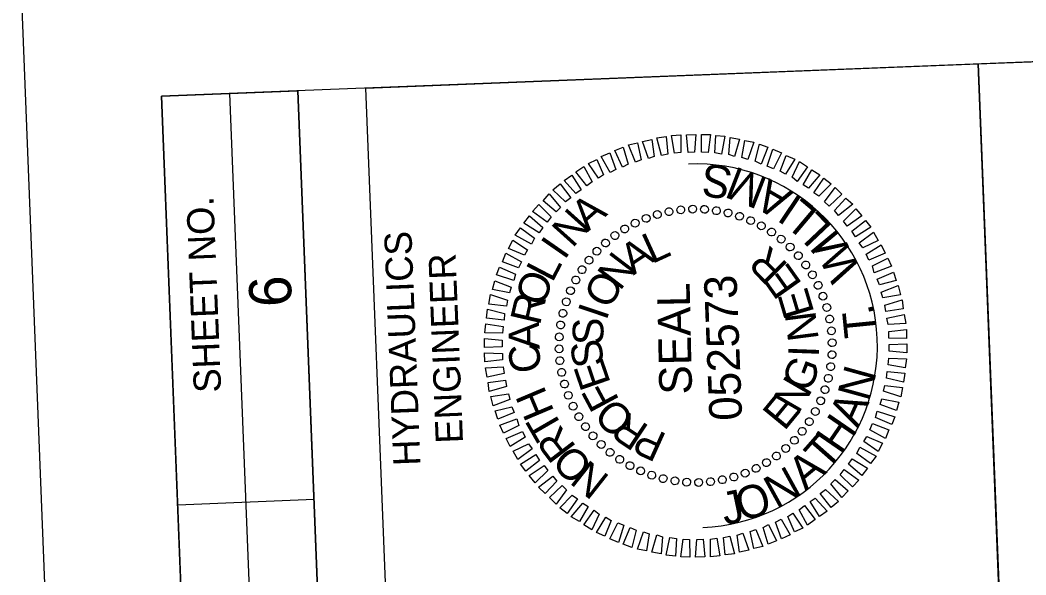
# Model space of a CAD drawing. Extents: x 1627804 to 1628970, y 763730 to 765944.
# Drawn here: x 1627803.6 to 1627988.3, y 765588.9 to 765690.7 of the extents above; entities that cross this region are included whole.
import ezdxf

# ---------------------------------------------------------------- set-up
doc = ezdxf.new("R2010")
doc.units = 0
for name, color, linetype in [('Exist Property Line Text', 7, 'Continuous'), ('Exist Property Owner Number CELL', 7, 'Continuous'), ('Exist Right of Way Easement Line', 7, 'Continuous'), ('Exist Right of Way Monument Text', 7, 'Continuous'), ('Exist Utilities Gas UG Line', 7, 'Continuous'), ('Exist Utilities Gas UG Line Text', 7, 'Continuous'), ('Raster_Level_0', 7, 'Continuous'), ('Scratch_Level_2', 7, 'Continuous')]:
    doc.layers.add(name, color=color, linetype=linetype)

msp = doc.modelspace()

# ---------------------------------------------------------------- linework, layer by layer
at = {"layer": 'Exist Property Owner Number CELL'}
msp.add_arc((1627927.63, 765630.96), 33.36, 272.2582, 92.2582, dxfattribs=at)
at = {"layer": 'Exist Right of Way Monument Text'}
for p, q in [((1627862.5, 765477.84), (1627854.61, 765677.73)), ((1627850.01, 765477.34), (1627842.12, 765677.24)), ((1627832.59, 765601.8), (1627857.57, 765602.79))]:
    msp.add_line(p, q, dxfattribs=at)
for points in [[(1627829.58, 765676.74), (1627888.69, 764177.91), (1628937.87, 764219.28), (1628878.77, 765718.12)], [(1627871.04, 765578.3), (1627867.1, 765678.22), (1627979.52, 765682.66), (1627983.46, 765582.73)], [(1627837.47, 765476.85), (1627829.58, 765676.74), (1627854.61, 765677.73), (1627862.5, 765477.84)]]:
    msp.add_lwpolyline(points, close=True, dxfattribs=at)
at = {"layer": 'Exist Utilities Gas UG Line'}
msp.add_lwpolyline([(1628969.75, 764045.4), (1628902.76, 765744.08), (1627803.62, 765700.74), (1627870.6, 764002.06)], close=True, dxfattribs=at)
at = {"layer": 'Exist Utilities Gas UG Line Text'}
for p, q in [((1627979.52, 765682.66), (1628011.47, 765683.92)), ((1627987.38, 765482.76), (1627979.5, 765682.65))]:
    msp.add_line(p, q, dxfattribs=at)
at = {"layer": 'Scratch_Level_2'}
for p, q in [((1627922.76, 765655.53), (1627922.76, 765655.53)), ((1627924.89, 765655.92), (1627924.89, 765655.92)), ((1627927.09, 765656.05), (1627927.09, 765656.05)), ((1627929.3, 765655.99), (1627929.3, 765655.99)), ((1627931.46, 765655.73), (1627931.46, 765655.73)), ((1627933.57, 765655.36), (1627933.57, 765655.36)), ((1627916.53, 765653.49), (1627916.53, 765653.49)), ((1627918.5, 765654.36), (1627918.5, 765654.36)), ((1627920.58, 765655.05), (1627920.58, 765655.05)), ((1627935.7, 765654.74), (1627935.7, 765654.74)), ((1627937.73, 765653.92), (1627937.73, 765653.92)), ((1627914.62, 765652.41), (1627914.62, 765652.41)), ((1627939.72, 765653), (1627939.72, 765653)), ((1627941.57, 765651.82), (1627941.57, 765651.82)), ((1627911.07, 765649.87), (1627911.07, 765649.87)), ((1627912.77, 765651.19), (1627912.77, 765651.19)), ((1627943.37, 765650.54), (1627943.37, 765650.54)), ((1627909.48, 765648.3), (1627909.48, 765648.3)), ((1627944.98, 765649.1), (1627944.98, 765649.1)), ((1627908.04, 765646.7), (1627908.04, 765646.7)), ((1627946.54, 765647.51), (1627946.54, 765647.51)), ((1627906.76, 765644.89), (1627906.76, 765644.89)), ((1627947.86, 765645.81), (1627947.86, 765645.81)), ((1627905.59, 765643.05), (1627905.59, 765643.05)), ((1627949.08, 765643.96), (1627949.08, 765643.96)), ((1627904.66, 765641.06), (1627904.66, 765641.06)), ((1627950.16, 765642.05), (1627950.16, 765642.05)), ((1627903.84, 765639.02), (1627903.84, 765639.02)), ((1627951.04, 765640.08), (1627951.04, 765640.08)), ((1627903.23, 765636.9), (1627903.23, 765636.9)), ((1627951.72, 765638.01), (1627951.72, 765638.01)), ((1627952.21, 765635.83), (1627952.21, 765635.83)), ((1627902.86, 765634.78), (1627902.86, 765634.78)), ((1627952.59, 765633.69), (1627952.59, 765633.69)), ((1627902.6, 765632.62), (1627902.6, 765632.62)), ((1627952.73, 765631.49), (1627952.73, 765631.49)), ((1627902.53, 765630.42), (1627902.53, 765630.42)), ((1627927.63, 765630.96), (1627927.63, 765630.96)), ((1627952.67, 765629.29), (1627952.67, 765629.29)), ((1627902.67, 765628.22), (1627902.67, 765628.22)), ((1627903.05, 765626.08), (1627903.05, 765626.08)), ((1627952.4, 765627.13), (1627952.4, 765627.13)), ((1627903.54, 765623.9), (1627903.54, 765623.9)), ((1627952.03, 765625.01), (1627952.03, 765625.01)), ((1627951.42, 765622.89), (1627951.42, 765622.89)), ((1627904.22, 765621.83), (1627904.22, 765621.83)), ((1627950.6, 765620.85), (1627950.6, 765620.85)), ((1627905.1, 765619.86), (1627905.1, 765619.86)), ((1627949.67, 765618.86), (1627949.67, 765618.86)), ((1627906.18, 765617.95), (1627906.18, 765617.95)), ((1627948.5, 765617.02), (1627948.5, 765617.02)), ((1627907.4, 765616.1), (1627907.4, 765616.1)), ((1627947.22, 765615.21), (1627947.22, 765615.21)), ((1627908.72, 765614.4), (1627908.72, 765614.4)), ((1627910.28, 765612.81), (1627910.28, 765612.81)), ((1627945.78, 765613.61), (1627945.78, 765613.61)), ((1627911.89, 765611.37), (1627911.89, 765611.37)), ((1627944.19, 765612.04), (1627944.19, 765612.04)), ((1627913.69, 765610.09), (1627913.69, 765610.09)), ((1627940.64, 765609.5), (1627940.64, 765609.5)), ((1627942.49, 765610.73), (1627942.49, 765610.73)), ((1627915.54, 765608.91), (1627915.54, 765608.91)), ((1627917.53, 765607.99), (1627917.53, 765607.99)), ((1627919.56, 765607.17), (1627919.56, 765607.17)), ((1627936.76, 765607.55), (1627936.76, 765607.55)), ((1627938.73, 765608.43), (1627938.73, 765608.43)), ((1627921.69, 765606.55), (1627921.69, 765606.55)), ((1627923.8, 765606.19), (1627923.8, 765606.19)), ((1627925.97, 765605.92), (1627925.97, 765605.92)), ((1627928.17, 765605.86), (1627928.17, 765605.86)), ((1627930.37, 765605.99), (1627930.37, 765605.99)), ((1627932.5, 765606.38), (1627932.5, 765606.38)), ((1627934.69, 765606.86), (1627934.69, 765606.86))]:
    msp.add_line(p, q, dxfattribs=at)
for points in [[(1627916.59, 765664.65), (1627915.32, 765667.8), (1627916.96, 765668.16), (1627917.63, 765665.04)], [(1627918.97, 765665.34), (1627917.9, 765668.45), (1627919.58, 765668.82), (1627920.01, 765665.68)], [(1627921.35, 765665.88), (1627920.52, 765669.1), (1627922.21, 765669.32), (1627922.54, 765666.13)], [(1627923.74, 765666.28), (1627923.21, 765669.51), (1627924.9, 765669.68), (1627924.93, 765666.43)], [(1627926.23, 765666.43), (1627925.95, 765669.67), (1627927.65, 765669.74), (1627927.43, 765666.48)], [(1627928.73, 765666.48), (1627928.7, 765669.73), (1627930.36, 765669.69), (1627929.93, 765666.42)], [(1627931.14, 765666.32), (1627931.31, 765669.53), (1627933.02, 765669.4), (1627932.35, 765666.12)], [(1627933.7, 765666.02), (1627933.98, 765669.14), (1627935.69, 765668.85), (1627934.77, 765665.66)], [(1627936.13, 765665.47), (1627936.65, 765668.59), (1627938.32, 765668.31), (1627937.19, 765665.11)], [(1627911.91, 765662.76), (1627910.3, 765665.65), (1627911.87, 765666.36), (1627912.99, 765663.3)], [(1627914.23, 765663.75), (1627912.81, 765666.75), (1627914.34, 765667.36), (1627915.26, 765664.29)], [(1627938.55, 765664.81), (1627939.33, 765667.95), (1627940.91, 765667.36), (1627939.63, 765664.3)], [(1627940.79, 765663.9), (1627941.82, 765667.04), (1627943.4, 765666.35), (1627941.91, 765663.44)], [(1627909.81, 765661.68), (1627907.95, 765664.41), (1627909.47, 765665.12), (1627910.73, 765662.31)], [(1627943.13, 765662.99), (1627944.27, 765665.89), (1627945.85, 765665.2), (1627944.1, 765662.43)], [(1627945.33, 765661.88), (1627946.71, 765664.73), (1627948.15, 765663.79), (1627946.26, 765661.11)], [(1627907.66, 765660.29), (1627905.66, 765662.86), (1627907.12, 765663.87), (1627908.63, 765661.03)], [(1627947.38, 765660.46), (1627948.98, 765663.22), (1627950.46, 765662.33), (1627948.36, 765659.84)], [(1627903.77, 765657.34), (1627901.43, 765659.55), (1627902.74, 765660.65), (1627904.74, 765658.07)], [(1627905.66, 765658.91), (1627903.47, 765661.28), (1627904.88, 765662.28), (1627906.59, 765659.55)], [(1627949.34, 765659.03), (1627951.19, 765661.71), (1627952.53, 765660.66), (1627950.27, 765658.37)], [(1627902.04, 765655.52), (1627899.61, 765657.57), (1627900.76, 765658.82), (1627902.81, 765656.3)], [(1627951.31, 765657.36), (1627953.26, 765659.99), (1627954.45, 765658.78), (1627952.14, 765656.59)], [(1627953.12, 765655.78), (1627955.23, 765658.06), (1627956.48, 765656.91), (1627953.86, 765654.86)], [(1627900.36, 765653.65), (1627897.69, 765655.59), (1627898.84, 765656.84), (1627901.08, 765654.63)], [(1627954.75, 765653.84), (1627957.06, 765656.08), (1627958.17, 765654.78), (1627955.44, 765652.92)], [(1627898.89, 765651.69), (1627896.07, 765653.43), (1627897.12, 765654.77), (1627899.55, 765652.67)], [(1627956.32, 765652), (1627958.8, 765653.95), (1627959.8, 765652.69), (1627956.97, 765650.93)], [(1627897.47, 765649.58), (1627894.51, 765651.22), (1627895.5, 765652.56), (1627898.03, 765650.7)], [(1627957.66, 765649.85), (1627960.28, 765651.81), (1627961.14, 765650.29), (1627958.3, 765648.93)], [(1627896.2, 765647.58), (1627893.3, 765648.82), (1627894.09, 765650.35), (1627896.76, 765648.55)], [(1627895.14, 765645.24), (1627892.15, 765646.37), (1627892.78, 765647.95), (1627895.65, 765646.36)], [(1627958.94, 765647.75), (1627961.68, 765649.46), (1627962.44, 765647.94), (1627959.44, 765646.67)], [(1627960.08, 765645.6), (1627962.93, 765647.01), (1627963.58, 765645.53), (1627960.43, 765644.36)], [(1627894.28, 765642.95), (1627891.09, 765643.98), (1627891.63, 765645.4), (1627894.59, 765644.11)], [(1627960.97, 765643.18), (1627963.93, 765644.45), (1627964.44, 765642.91), (1627961.37, 765642.14)], [(1627893.47, 765640.67), (1627890.34, 765641.29), (1627890.78, 765642.86), (1627893.78, 765641.73)], [(1627961.72, 765640.81), (1627964.82, 765641.98), (1627965.24, 765640.29), (1627962.01, 765639.77)], [(1627892.92, 765638.24), (1627889.65, 765638.61), (1627889.98, 765640.33), (1627893.12, 765639.3)], [(1627962.36, 765638.43), (1627965.53, 765639.36), (1627965.74, 765637.71), (1627962.56, 765637.24)], [(1627892.47, 765635.67), (1627889.25, 765636), (1627889.44, 765637.66), (1627892.57, 765636.88)], [(1627962.76, 765636.04), (1627965.93, 765636.72), (1627966.2, 765635.03), (1627962.95, 765634.85)], [(1627892.16, 765633.26), (1627888.91, 765633.33), (1627889.14, 765634.99), (1627892.31, 765634.47)], [(1627963.11, 765633.56), (1627966.34, 765633.93), (1627966.36, 765632.28), (1627963.1, 765632.35)], [(1627892.11, 765630.76), (1627888.86, 765630.63), (1627888.85, 765632.28), (1627892.11, 765631.96)], [(1627963.15, 765631.16), (1627966.4, 765631.28), (1627966.41, 765629.63), (1627963.15, 765629.95)], [(1627892.16, 765628.36), (1627888.92, 765627.98), (1627888.9, 765629.63), (1627892.16, 765629.56)], [(1627963.1, 765628.65), (1627966.35, 765628.58), (1627966.12, 765626.92), (1627962.95, 765627.44)], [(1627892.5, 765625.87), (1627889.33, 765625.19), (1627889.06, 765626.88), (1627892.31, 765627.06)], [(1627962.79, 765626.24), (1627966.01, 765625.91), (1627965.82, 765624.26), (1627962.69, 765625.03)], [(1627892.9, 765623.48), (1627889.73, 765622.56), (1627889.52, 765624.2), (1627892.7, 765624.67)], [(1627893.54, 765621.1), (1627890.44, 765619.93), (1627890.02, 765621.62), (1627893.25, 765622.14)], [(1627962.34, 765623.67), (1627965.61, 765623.3), (1627965.28, 765621.58), (1627962.14, 765622.61)], [(1627961.79, 765621.24), (1627964.92, 765620.62), (1627964.48, 765619.05), (1627961.48, 765620.18)], [(1627894.29, 765618.73), (1627891.33, 765617.46), (1627890.82, 765619), (1627893.89, 765619.77)], [(1627960.98, 765618.96), (1627964.17, 765617.94), (1627963.63, 765616.51), (1627960.67, 765617.8)], [(1627895.18, 765616.32), (1627892.34, 765614.9), (1627891.68, 765616.38), (1627894.83, 765617.55)], [(1627960.12, 765616.67), (1627963.12, 765615.54), (1627962.48, 765613.97), (1627959.61, 765615.55)], [(1627896.32, 765614.16), (1627893.58, 765612.45), (1627892.82, 765613.97), (1627895.82, 765615.24)], [(1627897.6, 765612.06), (1627894.98, 765610.1), (1627894.12, 765611.62), (1627896.96, 765612.98)], [(1627959.06, 765614.33), (1627961.96, 765613.09), (1627961.17, 765611.56), (1627958.5, 765613.36)], [(1627898.94, 765609.91), (1627896.46, 765607.96), (1627895.46, 765609.22), (1627898.29, 765610.98)], [(1627957.79, 765612.33), (1627960.75, 765610.69), (1627959.76, 765609.35), (1627957.23, 765611.21)], [(1627900.51, 765608.07), (1627898.2, 765605.83), (1627897.1, 765607.13), (1627899.82, 765608.99)], [(1627956.37, 765610.22), (1627959.19, 765608.48), (1627958.14, 765607.14), (1627955.71, 765609.24)], [(1627954.9, 765608.26), (1627957.57, 765606.32), (1627956.42, 765605.07), (1627954.18, 765607.28)], [(1627902.14, 765606.13), (1627900.03, 765603.85), (1627898.78, 765605), (1627901.4, 765607.05)], [(1627903.95, 765604.55), (1627902, 765601.92), (1627900.81, 765603.13), (1627903.12, 765605.32)], [(1627953.22, 765606.39), (1627955.65, 765604.34), (1627954.5, 765603.09), (1627952.45, 765605.61)], [(1627905.92, 765602.88), (1627904.07, 765600.2), (1627902.73, 765601.25), (1627904.99, 765603.54)], [(1627951.49, 765604.57), (1627953.83, 765602.37), (1627952.52, 765601.26), (1627950.52, 765603.84)], [(1627907.88, 765601.45), (1627906.29, 765598.69), (1627904.8, 765599.58), (1627906.9, 765602.07)], [(1627947.6, 765601.62), (1627949.6, 765599.05), (1627948.14, 765598.04), (1627946.63, 765600.88)], [(1627949.6, 765603), (1627951.79, 765600.63), (1627950.38, 765599.63), (1627948.67, 765602.36)], [(1627909.93, 765600.03), (1627908.55, 765597.18), (1627907.11, 765598.12), (1627909, 765600.8)], [(1627945.45, 765600.23), (1627947.31, 765597.5), (1627945.79, 765596.79), (1627944.53, 765599.6)], [(1627912.13, 765598.92), (1627910.99, 765596.02), (1627909.42, 765596.71), (1627911.16, 765599.48)], [(1627914.47, 765598.01), (1627913.44, 765594.87), (1627911.86, 765595.56), (1627913.35, 765598.47)], [(1627941.03, 765598.16), (1627942.45, 765595.16), (1627940.93, 765594.55), (1627940, 765597.62)], [(1627943.35, 765599.15), (1627944.96, 765596.26), (1627943.39, 765595.55), (1627942.27, 765598.61)], [(1627916.71, 765597.1), (1627915.93, 765593.97), (1627914.35, 765594.55), (1627915.64, 765597.61)], [(1627919.13, 765596.44), (1627918.61, 765593.32), (1627916.94, 765593.61), (1627918.07, 765596.8)], [(1627921.56, 765595.89), (1627921.28, 765592.78), (1627919.57, 765593.06), (1627920.49, 765596.25)], [(1627933.91, 765596.03), (1627934.74, 765592.81), (1627933.05, 765592.59), (1627932.72, 765595.78)], [(1627936.29, 765596.57), (1627937.37, 765593.46), (1627935.68, 765593.09), (1627935.25, 765596.23)], [(1627938.67, 765597.26), (1627939.94, 765594.11), (1627938.3, 765593.75), (1627937.63, 765596.87)], [(1627924.12, 765595.59), (1627923.95, 765592.38), (1627922.24, 765592.51), (1627922.91, 765595.79)], [(1627926.53, 765595.43), (1627926.56, 765592.18), (1627924.9, 765592.22), (1627925.33, 765595.49)], [(1627929.03, 765595.48), (1627929.31, 765592.24), (1627927.61, 765592.17), (1627927.83, 765595.44)], [(1627931.53, 765595.63), (1627932.05, 765592.4), (1627930.36, 765592.23), (1627930.33, 765595.48)]]:
    msp.add_lwpolyline(points, close=True, dxfattribs=at)
for centre, major_axis in [((1627918.54, 765654.33), (-0.261, 0.671)), ((1627920.61, 765655.03), (-0.202, 0.691)), ((1627922.73, 765655.55), (-0.141, 0.706)), ((1627924.9, 765655.89), (-0.078, 0.716)), ((1627927.08, 765656.03), (-0.016, 0.72)), ((1627929.27, 765655.98), (0.047, 0.718)), ((1627931.44, 765655.74), (0.109, 0.712)), ((1627933.59, 765655.32), (0.171, 0.699)), ((1627935.69, 765654.71), (0.231, 0.682)), ((1627916.53, 765653.45), (-0.319, 0.646)), ((1627937.73, 765653.91), (0.29, 0.659)), ((1627939.69, 765652.95), (0.346, 0.631)), ((1627912.8, 765651.18), (-0.426, 0.581)), ((1627914.62, 765652.39), (-0.374, 0.615)), ((1627941.56, 765651.81), (0.4, 0.599)), ((1627911.09, 765649.81), (-0.475, 0.541)), ((1627943.33, 765650.52), (0.451, 0.562)), ((1627944.97, 765649.07), (0.498, 0.52)), ((1627909.51, 765648.3), (-0.52, 0.498)), ((1627946.48, 765647.49), (0.541, 0.475)), ((1627908.07, 765646.65), (-0.562, 0.451)), ((1627947.85, 765645.79), (0.581, 0.426)), ((1627906.78, 765644.89), (-0.599, 0.4)), ((1627949.07, 765643.97), (0.615, 0.374)), ((1627905.64, 765643.02), (-0.631, 0.346)), ((1627950.12, 765642.05), (0.646, 0.319)), ((1627904.67, 765641.05), (-0.659, 0.29)), ((1627951, 765640.05), (0.671, 0.261)), ((1627903.88, 765639.01), (-0.682, 0.231)), ((1627951.71, 765637.98), (0.691, 0.202)), ((1627903.27, 765636.91), (-0.699, 0.171)), ((1627902.84, 765634.77), (-0.712, 0.109)), ((1627952.23, 765635.85), (0.706, 0.141)), ((1627902.6, 765632.59), (-0.718, 0.047)), ((1627952.56, 765633.69), (0.716, 0.078)), ((1627902.56, 765630.4), (-0.72, -0.016)), ((1627952.7, 765631.51), (0.72, 0.016)), ((1627952.66, 765629.32), (0.718, -0.047)), ((1627902.7, 765628.22), (-0.716, -0.078)), ((1627952.42, 765627.14), (0.712, -0.109)), ((1627903.03, 765626.06), (-0.706, -0.141)), ((1627951.99, 765625), (0.699, -0.171)), ((1627903.55, 765623.93), (-0.691, -0.202)), ((1627904.26, 765621.86), (-0.671, -0.261)), ((1627951.38, 765622.9), (0.682, -0.231)), ((1627905.14, 765619.86), (-0.646, -0.319)), ((1627950.59, 765620.86), (0.659, -0.29)), ((1627906.19, 765617.94), (-0.615, -0.374)), ((1627949.62, 765618.9), (0.631, -0.346)), ((1627907.41, 765616.12), (-0.581, -0.426)), ((1627948.49, 765617.02), (0.599, -0.4)), ((1627908.78, 765614.42), (-0.541, -0.475)), ((1627947.19, 765615.26), (0.562, -0.451)), ((1627910.29, 765612.84), (-0.498, -0.52)), ((1627944.17, 765612.1), (0.475, -0.541)), ((1627945.75, 765613.61), (0.52, -0.498)), ((1627911.93, 765611.39), (-0.451, -0.562)), ((1627913.7, 765610.1), (-0.4, -0.599)), ((1627942.46, 765610.73), (0.426, -0.581)), ((1627915.57, 765608.97), (-0.346, -0.631)), ((1627938.73, 765608.46), (0.319, -0.646)), ((1627940.64, 765609.52), (0.374, -0.615)), ((1627917.53, 765608), (-0.29, -0.659)), ((1627919.57, 765607.21), (-0.231, -0.682)), ((1627921.67, 765606.59), (-0.171, -0.699)), ((1627932.53, 765606.36), (0.141, -0.706)), ((1627934.65, 765606.88), (0.202, -0.691)), ((1627936.72, 765607.58), (0.261, -0.671)), ((1627923.82, 765606.17), (-0.109, -0.712)), ((1627925.99, 765605.93), (-0.047, -0.718)), ((1627928.18, 765605.88), (0.016, -0.72)), ((1627930.36, 765606.02), (0.078, -0.716))]:
    msp.add_ellipse(centre, major_axis=major_axis, ratio=0.999708, dxfattribs=at)

# ---------------------------------------------------------------- texts
at = {"layer": 'Exist Property Line Text'}
msp.add_text('6', height=7.75, rotation=92.2582, dxfattribs=at).set_placement((1627853.52, 765638.21))
at = {"layer": 'Exist Right of Way Easement Line'}
for s, rotation, p in [('S', 170.5234, (1627934.65, 765663.61)), ('M', 158.8769, (1627941.1, 765661.52)), ('A', 149.947, (1627945.68, 765659.06)), ('I', 146.1065, (1627947.52, 765657.79)), ('L', 139.7681, (1627950.36, 765655.43)), ('L', 133.4297, (1627952.92, 765652.77)), ('I', 129.5892, (1627954.33, 765651.03)), ('W', 116.928, (1627958.08, 765644.69)), ('T', 95.6803, (1627960.98, 765632.72)), ('.', 102.5495, (1627960.53, 765636.7)), ('N', 74.5419, (1627959.38, 765620.57)), ('A', 65.6119, (1627957.38, 765615.77)), ('H', 55.5267, (1627954.26, 765610.8)), ('T', 48.6575, (1627951.66, 765607.76)), ('A', 39.7275, (1627947.77, 765604.31)), ('N', 28.8929, (1627942.4, 765601)), ('O', 17.2153, (1627936.03, 765598.63)), ('J', 11.9042, (1627933, 765597.99))]:
    msp.add_text(s, height=6, rotation=rotation, dxfattribs=at).set_placement(p)
at = {"layer": 'Exist Right of Way Monument Text'}
for s, p in [('SHEET NO.', (1627840.53, 765622.43)), ('HYDRAULICS', (1627877.14, 765609.01)), ('ENGINEER', (1627884.93, 765613.12))]:
    msp.add_text(s, height=5, rotation=92.2582, dxfattribs=at).set_placement(p)
at = {"layer": 'Raster_Level_0'}
msp.add_text('052573', height=5.998, rotation=92.2582, dxfattribs=at).set_placement((1627936.18, 765617.33))
at = {"layer": 'Scratch_Level_2'}
for s, height, rotation, p in [('A', 5.64, 40.8753, (1627907.84, 765651.79)), ('N', 5.64, 48.0771, (1627905.01, 765648.73)), ('L', 5.64, 24.659, (1627919.59, 765645.9)), ('I', 5.64, 55.2783, (1627903.55, 765646.52)), ('A', 5.64, 34.0185, (1627916.21, 765643.82)), ('N', 5.64, 52.7348, (1627913.73, 765640.87)), ('R', 5.64, 134.7396, (1627944.81, 765645.74)), ('L', 5.64, 62.4791, (1627901.31, 765642.38)), ('E', 5.64, 125.3823, (1627947.3, 765642.29)), ('O', 5.64, 69.6794, (1627899.63, 765637.91)), ('O', 5.64, 62.0917, (1627911.86, 765637.44)), ('SEAL', 5.998, 91.2582, (1627926.98, 765622.07)), ('R', 5.64, 76.8793, (1627899.02, 765634.53)), ('E', 5.64, 106.67, (1627949.46, 765637.07)), ('I', 5.64, 71.4478, (1627911.24, 765635.41)), ('N', 5.64, 97.3146, (1627950.25, 765632.15)), ('A', 5.64, 91.2785, (1627898.98, 765630.33)), ('S', 5.64, 90.1586, (1627910.71, 765631.09)), ('C', 5.64, 98.4781, (1627899.44, 765626.39)), ('S', 5.64, 99.5138, (1627910.9, 765627.49)), ('I', 5.64, 87.9594, (1627950.23, 765628.79)), ('E', 5.64, 108.8693, (1627912.09, 765624.09)), ('G', 5.64, 69.2484, (1627948.59, 765622.17)), ('N', 5.64, 59.8921, (1627946.49, 765618.29)), ('H', 5.64, 112.8777, (1627901.74, 765618.88)), ('F', 5.64, 118.2252, (1627913.71, 765620.95)), ('E', 5.64, 50.5351, (1627943.91, 765615.18)), ('O', 5.64, 136.9394, (1627916.79, 765617.77)), ('R', 5.64, 146.2978, (1627919.31, 765616.12)), ('T', 5.64, 120.078, (1627903.51, 765615.69)), ('R', 5.64, 127.2787, (1627905.85, 765612.38)), ('P', 5.64, 155.6571, (1627922.57, 765614.64)), ('O', 5.64, 134.4799, (1627909.08, 765609.06)), ('N', 5.64, 141.6817, (1627912.07, 765606.87))]:
    msp.add_text(s, height=height, rotation=rotation, dxfattribs=at).set_placement(p)

doc.saveas('drawing.dxf')
